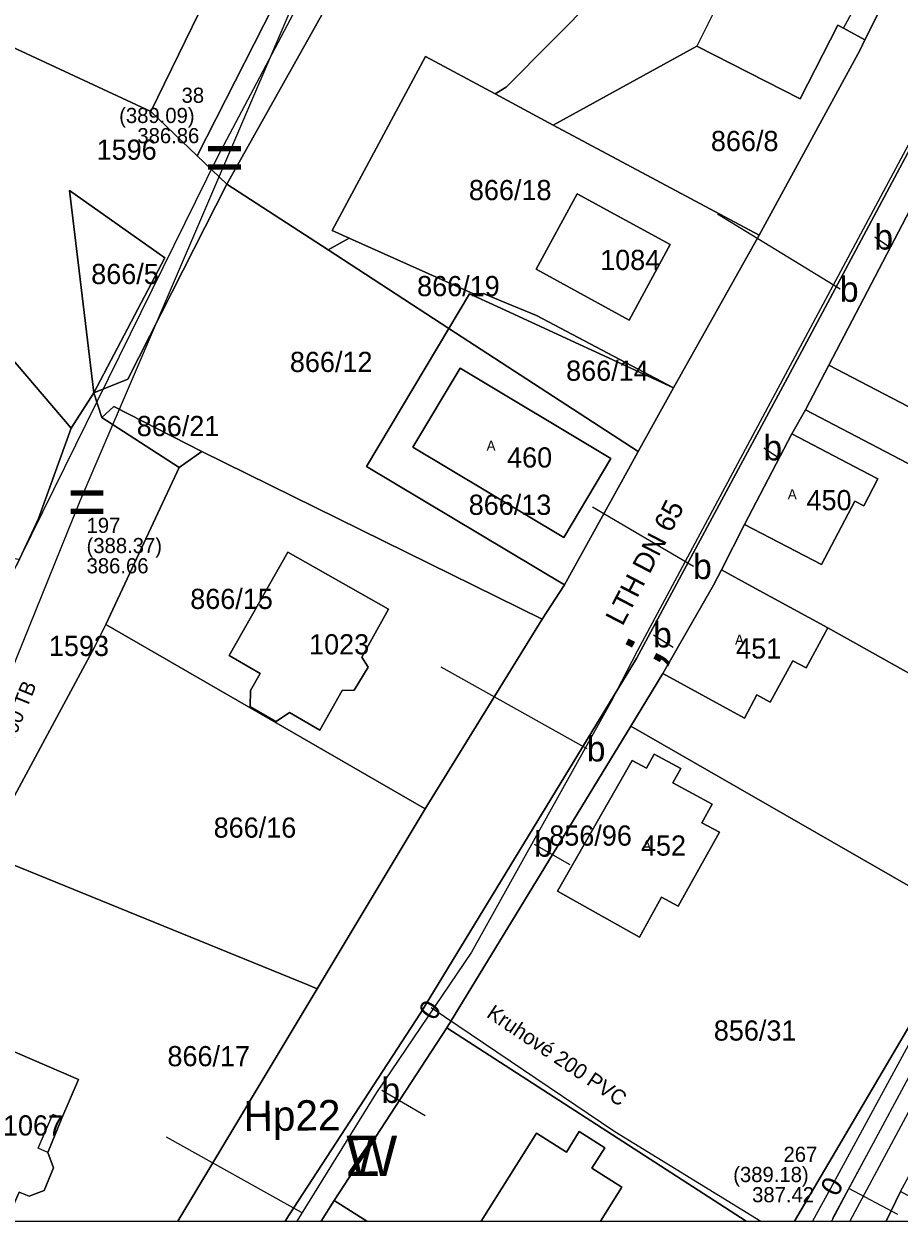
# Model space of a CAD drawing. Extents: x -564940 to -564406, y -1066466 to -1066072.
# Drawn here: x -564757.1 to -564670.5, y -1066465.6 to -1066347.1 of the extents above; entities that cross this region are included whole.
import ezdxf

# ---------------------------------------------------------------- set-up
doc = ezdxf.new("R2010")
doc.units = 0
for name, color, linetype in [('ft_g_5211', 7, 'Continuous'), ('ft_g_5451', 7, 'Continuous'), ('ft_g_5451_ft_g_5451_da_5452_gtc_da_5452', 7, 'Continuous'), ('ft_g_5751', 7, 'Continuous'), ('ft_g_6031', 7, 'Continuous'), ('ft_g_6040', 7, 'Continuous'), ('ft_g_6101', 7, 'Continuous'), ('ft_g_6101_ft_g_6101_da_6108_gtc_da_6108', 7, 'Continuous'), ('ft_g_gps_hydrant', 7, 'Continuous'), ('ft_g_gps_soupe_pri', 7, 'Continuous'), ('ft_g_stoka', 7, 'Continuous'), ('ft_g_stoka_ft_g_stoka_da_popis_gtc_da_6004', 7, 'Continuous'), ('ft_g_vrad', 7, 'Continuous'), ('ft_g_vrad_ft_g_vrad_da_popis_gtc_da_5091', 7, 'Continuous'), ('ft_parcela_polygon', 7, 'Continuous'), ('ft_parcela_text', 7, 'Continuous'), ('ft_stavebni_objekt_bod', 7, 'Continuous'), ('ft_stavebni_objekt_polygon', 7, 'Continuous')]:
    doc.layers.add(name, color=color, linetype=linetype)

msp = doc.modelspace()

# ---------------------------------------------------------------- linework, layer by layer
at = {"layer": 'ft_g_5211'}
for p, q in [((-564676.29, -1066373.34), (-564688.44, -1066365.9)), ((-564672.88, -1066368.16), (-564671.47, -1066369.12)), ((-564683.86, -1066389.04), (-564682.49, -1066389.93)), ((-564690.83, -1066400.8), (-564700.83, -1066394.93)), ((-564694.79, -1066407.56), (-564692.83, -1066408.78)), ((-564701.36, -1066418.86), (-564715.83, -1066410.78)), ((-564706.59, -1066428.29), (-564703.08, -1066430.32)), ((-564721.69, -1066452.68), (-564717.41, -1066455.18)), ((-564729.64, -1066464.79), (-564743.03, -1066457.31))]:
    msp.add_line(p, q, dxfattribs=at)
at = {"layer": 'ft_g_6040'}
for p, q in [((-564677.01, -1066465.34), (-564673.01, -1066457.88)), ((-564670.6, -1066464.98), (-564675.43, -1066462.4))]:
    msp.add_line(p, q, dxfattribs=at)
at = {"layer": 'ft_g_stoka'}
for p, q in [((-564718.59, -1066317.29), (-564751.59, -1066394.32)), ((-564716.03, -1066318.81), (-564737.98, -1066360.23)), ((-564737.98, -1066360.23), (-564759.65, -1066404.2)), ((-564751.59, -1066394.32), (-564765.68, -1066429.05))]:
    msp.add_line(p, q, dxfattribs=at)
for points in [[(-564553.41, -1066163.16), (-564553.48, -1066166.31), (-564548.89, -1066191.56), (-564549.63, -1066201.37), (-564551.36, -1066210.53), (-564553.55, -1066218.37), (-564556.52, -1066226.67), (-564558.83, -1066231.76), (-564567.86, -1066249.71), (-564582.71, -1066279.41), (-564586.53, -1066287.4), (-564596.46, -1066308.15), (-564604.5, -1066323.01), (-564613.83, -1066341.28), (-564619.05, -1066351.65), (-564629.23, -1066370.83), (-564638.15, -1066388.86), (-564652.7, -1066417.07), (-564664.74, -1066439.37), (-564677.25, -1066462.42), (-564679.03, -1066465.63)], [(-564654.2, -1066422.86), (-564664.94, -1066442.85), (-564667.42, -1066447.47), (-564675.37, -1066462.28), (-564677.17, -1066465.63)], [(-564716.8, -1066444.49), (-564698.62, -1066456.75), (-564684.14, -1066465.63)]]:
    msp.add_lwpolyline(points, dxfattribs=at)
at = {"layer": 'ft_g_vrad'}
for points in [[(-564620.48, -1066101.73), (-564620.18, -1066103.95), (-564620.08, -1066104.48), (-564611.19, -1066150.39), (-564610.58, -1066152.83), (-564605.15, -1066183.36), (-564606.08, -1066198.87), (-564617.93, -1066237.7), (-564621.76, -1066248.96), (-564630.12, -1066272.82), (-564643.79, -1066306.5), (-564659.26, -1066341.65), (-564662.1, -1066345.13), (-564696.41, -1066409.19)], [(-564573.05, -1066269.82), (-564574.29, -1066272.32), (-564577.91, -1066279.06), (-564602.05, -1066327.68), (-564604.48, -1066332.96), (-564632.28, -1066386.02), (-564638.67, -1066398.97), (-564652.45, -1066423.53), (-564669.32, -1066454.46), (-564675.34, -1066465.63)], [(-564696.41, -1066409.19), (-564698.99, -1066414.16), (-564712.82, -1066439.01)], [(-564712.82, -1066439.01), (-564722.22, -1066452.89), (-564730.1, -1066465.63)]]:
    msp.add_lwpolyline(points, dxfattribs=at)
at = {"layer": 'ft_parcela_polygon'}
for p, q in [((-564772.54, -1066465.63), (-564741.9, -1066465.63)), ((-564741.9, -1066465.63), (-564731.27, -1066465.63)), ((-564731.27, -1066465.63), (-564727.7, -1066465.63)), ((-564727.7, -1066465.63), (-564723.19, -1066465.63)), ((-564723.19, -1066465.63), (-564711.87, -1066465.63)), ((-564711.87, -1066465.63), (-564700.04, -1066465.63)), ((-564700.04, -1066465.63), (-564685.61, -1066465.63)), ((-564685.61, -1066465.63), (-564680.82, -1066465.63)), ((-564680.82, -1066465.63), (-564671.75, -1066465.63)), ((-564671.75, -1066465.63), (-564664.94, -1066465.63))]:
    msp.add_line(p, q, dxfattribs=at)
for points in [[(-564731.27, -1066465.63), (-564730.88, -1066465.02), (-564717.88, -1066445.03), (-564696.48, -1066409.93), (-564680.08, -1066379.48), (-564666.81, -1066354.64), (-564644.67, -1066309.69), (-564640.93, -1066302.01), (-564622.61, -1066246.86), (-564608.45, -1066209.76), (-564605.69, -1066192.25), (-564605.46, -1066182.07), (-564606.02, -1066175.01), (-564609.83, -1066156.99), (-564613.13, -1066141.3), (-564616.8, -1066123.25), (-564619.91, -1066107.51), (-564621.15, -1066099.64), (-564625.67, -1066074.88), (-564625.78, -1066072.02)], [(-564641.69, -1066277.26), (-564651.71, -1066302.17), (-564660.87, -1066321.4), (-564666.93, -1066334.54), (-564667.27, -1066335.3), (-564668.77, -1066338.53), (-564673.84, -1066348.65), (-564674.33, -1066349.63), (-564684.32, -1066367.99), (-564692.82, -1066383.11), (-564696.31, -1066389.42), (-564697.27, -1066391.15), (-564703.6, -1066402.63), (-564705.83, -1066406.02), (-564717.41, -1066424.81), (-564728.11, -1066442.62), (-564741.9, -1066465.63)], [(-564727.7, -1066465.63), (-564726.4, -1066463.6), (-564715.26, -1066446.5), (-564697.04, -1066416.62), (-564693.87, -1066411.41), (-564688.85, -1066402.64), (-564688.04, -1066401.15), (-564685.76, -1066396.63), (-564681.08, -1066387.68), (-564679.74, -1066385.3), (-564677.42, -1066380.87), (-564667.1, -1066361.1), (-564664.69, -1066356.49), (-564664.43, -1066355.85), (-564653.51, -1066333.95), (-564638.08, -1066303.01), (-564640.93, -1066302.01), (-564644.67, -1066309.69), (-564666.81, -1066354.64), (-564680.08, -1066379.48), (-564696.48, -1066409.93), (-564717.88, -1066445.03), (-564730.88, -1066465.02), (-564731.27, -1066465.63)], [(-564628.33, -1066465.63), (-564628.12, -1066465.26), (-564661.74, -1066446.92), (-564656.38, -1066437.43), (-564654.96, -1066434.92), (-564647.21, -1066420.91), (-564645.29, -1066417.18), (-564636.21, -1066399.34), (-564626.67, -1066381.79), (-564621.16, -1066371.09), (-564619.75, -1066368.35), (-564616.93, -1066362.92), (-564610.68, -1066350.52), (-564606.31, -1066341.84), (-564601.53, -1066332.64), (-564594.17, -1066318.35), (-564601.68, -1066315.73), (-564632.08, -1066373.21), (-564646.54, -1066402.48), (-564655.62, -1066419.11), (-564663.36, -1066435.96), (-564680.82, -1066465.63)], [(-564680.82, -1066465.63), (-564663.36, -1066435.96), (-564697.04, -1066416.62), (-564715.26, -1066446.5), (-564685.61, -1066465.63)], [(-564692.09, -1066420.82), (-564692.86, -1066422.23), (-564688.99, -1066424.33), (-564690, -1066426.18), (-564688.24, -1066427.13), (-564692.34, -1066434.46), (-564694.01, -1066433.55), (-564696.17, -1066437.51), (-564704.29, -1066432.97), (-564696.9, -1066420.03), (-564695.49, -1066420.79), (-564694.73, -1066419.39), (-564692.09, -1066420.82)], [(-564741.9, -1066465.63), (-564728.11, -1066442.62), (-564729.04, -1066442.24), (-564761.15, -1066429.16), (-564761.84, -1066430.27), (-564773.02, -1066449.63), (-564775.06, -1066453.15), (-564774.81, -1066464.4), (-564772.54, -1066465.63)], [(-564685.61, -1066465.63), (-564715.26, -1066446.5), (-564726.4, -1066463.6), (-564723.19, -1066465.63)], [(-564760.96, -1066447.66), (-564751.73, -1066451.62), (-564753.39, -1066455.44), (-564754.77, -1066458.83), (-564754.2, -1066460.37), (-564755.14, -1066462.59), (-564756.61, -1066463.17), (-564757.6, -1066462.76), (-564758.3, -1066464.37), (-564766.61, -1066460.8), (-564760.96, -1066447.66)], [(-564671.75, -1066465.63), (-564670.33, -1066462.7), (-564663.75, -1066450.61), (-564662.84, -1066451.11), (-564647.12, -1066459.81), (-564641.74, -1066462.71), (-564640.27, -1066463.52), (-564636.48, -1066465.63)], [(-564700.04, -1066465.63), (-564697.92, -1066462.27), (-564700.89, -1066460.4), (-564699.61, -1066458.37), (-564702.14, -1066456.77), (-564703.42, -1066458.8), (-564706.38, -1066456.93), (-564711.87, -1066465.63)], [(-564711.87, -1066465.63), (-564706.38, -1066456.93), (-564703.42, -1066458.8), (-564702.14, -1066456.77), (-564699.61, -1066458.37), (-564700.89, -1066460.4), (-564697.92, -1066462.27), (-564700.04, -1066465.63)], [(-564723.19, -1066465.63), (-564726.4, -1066463.6), (-564727.7, -1066465.63)], [(-564664.94, -1066465.63), (-564670.33, -1066462.7), (-564671.75, -1066465.63)]]:
    msp.add_lwpolyline(points, dxfattribs=at)
for points in [[(-564723.19, -1066311.93), (-564727.48, -1066309.75), (-564737.99, -1066304.53), (-564753.33, -1066300.23), (-564754.76, -1066307.54), (-564753.52, -1066307.88), (-564751.85, -1066301.99), (-564740.82, -1066305.04), (-564735.64, -1066307.98), (-564724.37, -1066314.34), (-564718.03, -1066317.92), (-564723.05, -1066326.81), (-564739.99, -1066360.12), (-564737.04, -1066362.92), (-564711.71, -1066317.76), (-564713.49, -1066316.85)], [(-564758.63, -1066327.35), (-564769.4, -1066344.34), (-564758.34, -1066349.33), (-564744.59, -1066355.75), (-564728.86, -1066323.53), (-564740.69, -1066316.86), (-564736.92, -1066310.24), (-564741.53, -1066307.59), (-564742.46, -1066310.95), (-564753.52, -1066307.88), (-564754.76, -1066307.54)], [(-564727.02, -1066369.44), (-564724.93, -1066368.29), (-564726.63, -1066367.53), (-564717.38, -1066350.28), (-564710.48, -1066353.98), (-564709.37, -1066353.33), (-564700.4, -1066344.24), (-564692, -1066327.75), (-564691.65, -1066326.97), (-564711.71, -1066317.76), (-564737.04, -1066362.92)], [(-564728.86, -1066323.53), (-564744.59, -1066355.75), (-564739.99, -1066360.12), (-564723.05, -1066326.81)], [(-564676.54, -1066347.19), (-564675.98, -1066347.47), (-564673.84, -1066348.65), (-564668.77, -1066338.53), (-564681.8, -1066331.74), (-564691.65, -1066326.97), (-564692, -1066327.75), (-564700.4, -1066344.24), (-564709.37, -1066353.33), (-564710.48, -1066353.98), (-564704.72, -1066357.08), (-564690.51, -1066349.28), (-564680.26, -1066354.5)], [(-564684.32, -1066367.99), (-564674.33, -1066349.63), (-564673.84, -1066348.65), (-564675.98, -1066347.47), (-564676.54, -1066347.19), (-564680.26, -1066354.5), (-564690.51, -1066349.28), (-564704.72, -1066357.08)], [(-564758.34, -1066349.33), (-564763.26, -1066356.76), (-564758.31, -1066360.26), (-564758.49, -1066362.14), (-564759.55, -1066373.09), (-564767.41, -1066372.33), (-564767.58, -1066374.04), (-564759.75, -1066378.58), (-564752.48, -1066387.1), (-564750.23, -1066383.61), (-564746.85, -1066382.26), (-564737.04, -1066362.92), (-564739.99, -1066360.12), (-564744.59, -1066355.75)], [(-564706.37, -1066375.96), (-564692.82, -1066383.11), (-564684.32, -1066367.99), (-564704.72, -1066357.08), (-564710.48, -1066353.98), (-564717.38, -1066350.28), (-564726.63, -1066367.53), (-564724.93, -1066368.29), (-564712.61, -1066373.79), (-564711.64, -1066373.76), (-564709.92, -1066374.48)], [(-564679.74, -1066385.3), (-564661.73, -1066394.69), (-564646.81, -1066365.78), (-564664.69, -1066356.49), (-564667.1, -1066361.1), (-564656.9, -1066366.42), (-564661.26, -1066374.76), (-564660.19, -1066375.31), (-564661.81, -1066378.41), (-564662.88, -1066377.86), (-564667.23, -1066386.19), (-564677.42, -1066380.87)], [(-564662.88, -1066377.86), (-564661.81, -1066378.41), (-564660.19, -1066375.31), (-564661.26, -1066374.76), (-564656.9, -1066366.42), (-564667.1, -1066361.1), (-564677.42, -1066380.87), (-564667.23, -1066386.19)], [(-564739.51, -1066389.41), (-564705.83, -1066406.02), (-564703.6, -1066402.63), (-564723.22, -1066390.91), (-564715.05, -1066377.23), (-564727.02, -1066369.44), (-564737.04, -1066362.92), (-564746.85, -1066382.26), (-564750.23, -1066383.61), (-564749.44, -1066386.03), (-564748.23, -1066384.97)], [(-564752.64, -1066363.55), (-564750.23, -1066383.61), (-564743.19, -1066370.24)], [(-564750.23, -1066383.61), (-564752.64, -1066363.55), (-564743.19, -1066370.24)], [(-564702.35, -1066363.9), (-564693.13, -1066368.92), (-564697.19, -1066376.39), (-564706.41, -1066371.37)], [(-564693.13, -1066368.92), (-564702.35, -1066363.9), (-564706.41, -1066371.37), (-564697.19, -1066376.39)], [(-564713, -1066373.8), (-564710.26, -1066375.06), (-564692.82, -1066383.11), (-564706.37, -1066375.96), (-564709.92, -1066374.48), (-564711.64, -1066373.76), (-564712.61, -1066373.79), (-564724.93, -1066368.29), (-564727.02, -1066369.44), (-564715.05, -1066377.23)], [(-564715.05, -1066377.23), (-564696.31, -1066389.42), (-564692.82, -1066383.11), (-564710.26, -1066375.06), (-564713, -1066373.8)], [(-564696.31, -1066389.42), (-564715.05, -1066377.23), (-564723.22, -1066390.91), (-564703.6, -1066402.63), (-564697.27, -1066391.15)], [(-564755.71, -1066396.05), (-564752.48, -1066387.1), (-564759.75, -1066378.58), (-564760.01, -1066380.77), (-564773.99, -1066378.49), (-564776.88, -1066377.29), (-564777.32, -1066381.57), (-564772.25, -1066382.16), (-564772.9, -1066387.55), (-564773.22, -1066387.53), (-564774.42, -1066388.48), (-564774.6, -1066390.1), (-564773.61, -1066391.31), (-564773.35, -1066391.34), (-564773.94, -1066396.66), (-564762.02, -1066398.05), (-564762.19, -1066399.54), (-564757.59, -1066400.08)], [(-564713.93, -1066381.17), (-564699.01, -1066390.11), (-564703.68, -1066397.92), (-564718.61, -1066388.98)], [(-564718.61, -1066388.98), (-564703.68, -1066397.92), (-564699.01, -1066390.11), (-564713.93, -1066381.17)], [(-564761.84, -1066430.27), (-564761.15, -1066429.16), (-564750.17, -1066408.79), (-564749.02, -1066406.55), (-564741.77, -1066391), (-564749.44, -1066386.03), (-564750.23, -1066383.61), (-564752.48, -1066387.1), (-564755.71, -1066396.05), (-564757.59, -1066400.08), (-564757.76, -1066400.45), (-564760.24, -1066404.88), (-564772.83, -1066426.25)], [(-564741.77, -1066391), (-564739.51, -1066389.41), (-564748.23, -1066384.97), (-564749.44, -1066386.03)], [(-564655.62, -1066419.11), (-564646.54, -1066402.48), (-564661.73, -1066394.69), (-564679.74, -1066385.3), (-564681.08, -1066387.68), (-564673.46, -1066391.66), (-564672.57, -1066392.13), (-564673.96, -1066394.79), (-564674.85, -1066394.32), (-564678.14, -1066400.61), (-564685.76, -1066396.63), (-564688.04, -1066401.15), (-564685.06, -1066402.78), (-564677.51, -1066406.89)], [(-564672.57, -1066392.13), (-564673.46, -1066391.66), (-564681.08, -1066387.68), (-564685.76, -1066396.63), (-564678.14, -1066400.61), (-564674.85, -1066394.32), (-564673.96, -1066394.79)], [(-564705.83, -1066406.02), (-564739.51, -1066389.41), (-564741.77, -1066391), (-564749.02, -1066406.55), (-564717.41, -1066424.81)], [(-564734.75, -1066414.66), (-564734.69, -1066413.08), (-564733.74, -1066411.39), (-564736.81, -1066409.61), (-564731, -1066399.37), (-564721.04, -1066405.03), (-564723.69, -1066409.77), (-564723.06, -1066410.78), (-564724.45, -1066413.06), (-564725.61, -1066413.1), (-564727.83, -1066417), (-564730.85, -1066415.28), (-564732.15, -1066416.14)], [(-564727.83, -1066417), (-564725.61, -1066413.1), (-564724.45, -1066413.06), (-564723.06, -1066410.78), (-564723.69, -1066409.77), (-564721.04, -1066405.03), (-564731, -1066399.37), (-564736.81, -1066409.61), (-564733.74, -1066411.39), (-564734.69, -1066413.08), (-564734.75, -1066414.66), (-564732.15, -1066416.14), (-564730.85, -1066415.28)], [(-564685.79, -1066415.82), (-564684.54, -1066413.53), (-564683.23, -1066414.25), (-564680.98, -1066410.13), (-564679.66, -1066410.84), (-564677.51, -1066406.89), (-564685.06, -1066402.78), (-564688.04, -1066401.15), (-564688.85, -1066402.64), (-564693.87, -1066411.41)], [(-564717.41, -1066424.81), (-564749.02, -1066406.55), (-564750.17, -1066408.79), (-564761.15, -1066429.16), (-564729.04, -1066442.24), (-564728.11, -1066442.62)], [(-564697.04, -1066416.62), (-564663.36, -1066435.96), (-564655.62, -1066419.11), (-564677.51, -1066406.89), (-564679.66, -1066410.84), (-564680.98, -1066410.13), (-564683.23, -1066414.25), (-564684.54, -1066413.53), (-564685.79, -1066415.82), (-564693.87, -1066411.41)], [(-564696.17, -1066437.51), (-564694.01, -1066433.55), (-564692.34, -1066434.46), (-564688.24, -1066427.13), (-564690, -1066426.18), (-564688.99, -1066424.33), (-564692.86, -1066422.23), (-564692.09, -1066420.82), (-564694.73, -1066419.39), (-564695.49, -1066420.79), (-564696.9, -1066420.03), (-564704.29, -1066432.97)], [(-564751.73, -1066451.62), (-564760.96, -1066447.66), (-564766.61, -1066460.8), (-564758.3, -1066464.37), (-564757.6, -1066462.76), (-564756.61, -1066463.17), (-564755.14, -1066462.59), (-564754.2, -1066460.37), (-564754.77, -1066458.83), (-564753.39, -1066455.44)]]:
    msp.add_lwpolyline(points, close=True, dxfattribs=at)
at = {"layer": 'ft_stavebni_objekt_polygon'}
msp.add_line((-564711.87, -1066465.63), (-564700.04, -1066465.63), dxfattribs=at)
for points in [[(-564675.63, -1066345.19), (-564671.95, -1066337.97), (-564682.2, -1066332.75), (-564685.29, -1066338.92), (-564687.38, -1066337.85), (-564689.52, -1066342.04), (-564687.42, -1066343.11), (-564690.51, -1066349.28), (-564680.26, -1066354.5), (-564676.54, -1066347.19), (-564675.98, -1066347.47), (-564674.96, -1066345.62)], [(-564667.1, -1066361.1), (-564677.42, -1066380.87), (-564667.23, -1066386.19), (-564662.88, -1066377.86), (-564661.81, -1066378.41), (-564660.19, -1066375.31), (-564661.26, -1066374.76), (-564656.9, -1066366.42)], [(-564706.41, -1066371.37), (-564697.19, -1066376.39), (-564693.13, -1066368.92), (-564702.35, -1066363.9)], [(-564713.93, -1066381.17), (-564718.61, -1066388.98), (-564703.68, -1066397.92), (-564699.01, -1066390.11)], [(-564685.76, -1066396.63), (-564678.14, -1066400.61), (-564674.85, -1066394.32), (-564673.96, -1066394.79), (-564672.57, -1066392.13), (-564673.46, -1066391.66), (-564681.08, -1066387.68)], [(-564736.81, -1066409.61), (-564733.74, -1066411.39), (-564734.69, -1066413.08), (-564734.75, -1066414.66), (-564732.15, -1066416.14), (-564730.85, -1066415.28), (-564727.83, -1066417), (-564725.61, -1066413.1), (-564724.45, -1066413.06), (-564723.06, -1066410.78), (-564723.69, -1066409.77), (-564721.04, -1066405.03), (-564731, -1066399.37)], [(-564684.54, -1066413.53), (-564683.23, -1066414.25), (-564680.98, -1066410.13), (-564679.66, -1066410.84), (-564677.51, -1066406.89), (-564685.06, -1066402.78), (-564688.04, -1066401.15), (-564688.85, -1066402.64), (-564693.87, -1066411.41), (-564685.79, -1066415.82)], [(-564688.24, -1066427.13), (-564690, -1066426.18), (-564688.99, -1066424.33), (-564692.86, -1066422.23), (-564692.09, -1066420.82), (-564694.73, -1066419.39), (-564695.49, -1066420.79), (-564696.9, -1066420.03), (-564704.29, -1066432.97), (-564696.17, -1066437.51), (-564694.01, -1066433.55), (-564692.34, -1066434.46)], [(-564766.61, -1066460.8), (-564758.3, -1066464.37), (-564757.6, -1066462.76), (-564756.61, -1066463.17), (-564755.14, -1066462.59), (-564754.2, -1066460.37), (-564754.77, -1066458.83), (-564755.72, -1066458.41), (-564754.27, -1066455.05), (-564753.39, -1066455.44), (-564751.73, -1066451.62), (-564760.96, -1066447.66)]]:
    msp.add_lwpolyline(points, close=True, dxfattribs=at)
msp.add_lwpolyline([(-564700.04, -1066465.63), (-564697.92, -1066462.27), (-564700.89, -1066460.4), (-564699.61, -1066458.37), (-564702.14, -1066456.77), (-564703.42, -1066458.8), (-564706.38, -1066456.93), (-564711.87, -1066465.63)], dxfattribs=at)

# ---------------------------------------------------------------- texts
at = {"layer": 'ft_g_5451'}
msp.add_text('Z', height=4, rotation=0.5947, dxfattribs=at).set_placement((-564725.19, -1066461.19))
at = {"layer": 'ft_g_5451_ft_g_5451_da_5452_gtc_da_5452'}
msp.add_text('Hp22', height=3, rotation=0.5947, dxfattribs=at).set_placement((-564735.37, -1066456.73))
at = {"layer": 'ft_g_5751'}
msp.add_text(';', height=5, rotation=62.5523, dxfattribs=at).set_placement((-564694.44, -1066410.82))
at = {"layer": 'ft_g_6031'}
for rotation, p in [(56.0055, (-564716.52, -1066445.89)), (241.2448, (-564677.65, -1066461.05))]:
    msp.add_text('0', height=2, rotation=rotation, dxfattribs=at).set_placement(p)
at = {"layer": 'ft_g_6101'}
for p in [(-564739.23, -1066362.73), (-564752.84, -1066396.82)]:
    msp.add_text('=', height=5, dxfattribs=at).set_placement(p)
at = {"layer": 'ft_g_6101_ft_g_6101_da_6108_gtc_da_6108'}
for s, p in [('38', (-564741.53, -1066354.88)), ('(389.09)', (-564747.71, -1066356.88)), ('386.86', (-564745.91, -1066358.88)), ('197', (-564750.94, -1066397.48)), ('(388.37)', (-564750.94, -1066399.48)), ('386.66', (-564750.94, -1066401.48)), ('267', (-564681.91, -1066459.77)), ('(389.18)', (-564686.89, -1066461.77)), ('387.42', (-564685.02, -1066463.77))]:
    msp.add_text(s, height=1.5, dxfattribs=at).set_placement(p)
at = {"layer": 'ft_g_gps_hydrant'}
msp.add_text('W', height=4, dxfattribs=at).set_placement((-564725.21, -1066461.18))
at = {"layer": 'ft_g_gps_soupe_pri'}
for p in [(-564672.92, -1066369.41), (-564676.33, -1066374.59), (-564683.9, -1066390.29), (-564690.87, -1066402.05), (-564694.83, -1066408.81), (-564701.4, -1066420.11), (-564706.63, -1066429.54), (-564721.73, -1066453.93)]:
    msp.add_text('b', height=2.5, dxfattribs=at).set_placement(p)
at = {"layer": 'ft_g_stoka_ft_g_stoka_da_popis_gtc_da_6004'}
for s, rotation, p in [('Kruhové 400 TB', 67.9187, (-564761.32, -1066425.96)), ('Kruhové 200 PVC', 326.0055, (-564711.42, -1066445.36))]:
    msp.add_text(s, height=1.5, rotation=rotation, dxfattribs=at).set_placement(p)
at = {"layer": 'ft_g_vrad_ft_g_vrad_da_popis_gtc_da_5091'}
msp.add_text('LTH DN 65', height=2, rotation=62.5523, dxfattribs=at).set_placement((-564697.86, -1066406.78))
at = {"layer": 'ft_parcela_text'}
for s, p in [('866/8', (-564689.1, -1066359.66)), ('1596', (-564749.94, -1066360.52)), ('866/18', (-564713.07, -1066364.52)), ('1084', (-564700.07, -1066371.44)), ('866/5', (-564750.48, -1066372.83)), ('866/19', (-564718.2, -1066374.03)), ('866/12', (-564730.8, -1066381.54)), ('866/14', (-564703.44, -1066382.41)), ('866/21', (-564745.97, -1066387.89)), ('460', (-564709.29, -1066391)), ('866/13', (-564713.09, -1066395.69)), ('450', (-564679.63, -1066395.23)), ('866/15', (-564740.67, -1066405.01)), ('1593', (-564754.67, -1066409.67)), ('1023', (-564728.9, -1066409.51)), ('451', (-564686.6, -1066409.92)), ('866/16', (-564738.35, -1066427.66)), ('856/96', (-564705.11, -1066428.45)), ('452', (-564696.03, -1066429.44)), ('856/31', (-564688.81, -1066447.76)), ('866/17', (-564742.93, -1066450.3)), ('1067', (-564759.22, -1066457.16))]:
    msp.add_text(s, height=2, dxfattribs=at).set_placement(p)
at = {"layer": 'ft_stavebni_objekt_bod'}
for p in [(-564711.32, -1066389.34), (-564681.49, -1066394.15), (-564686.72, -1066408.56), (-564695.9, -1066428.93)]:
    msp.add_text('A', height=1, dxfattribs=at).set_placement(p)

doc.saveas('drawing.dxf')
